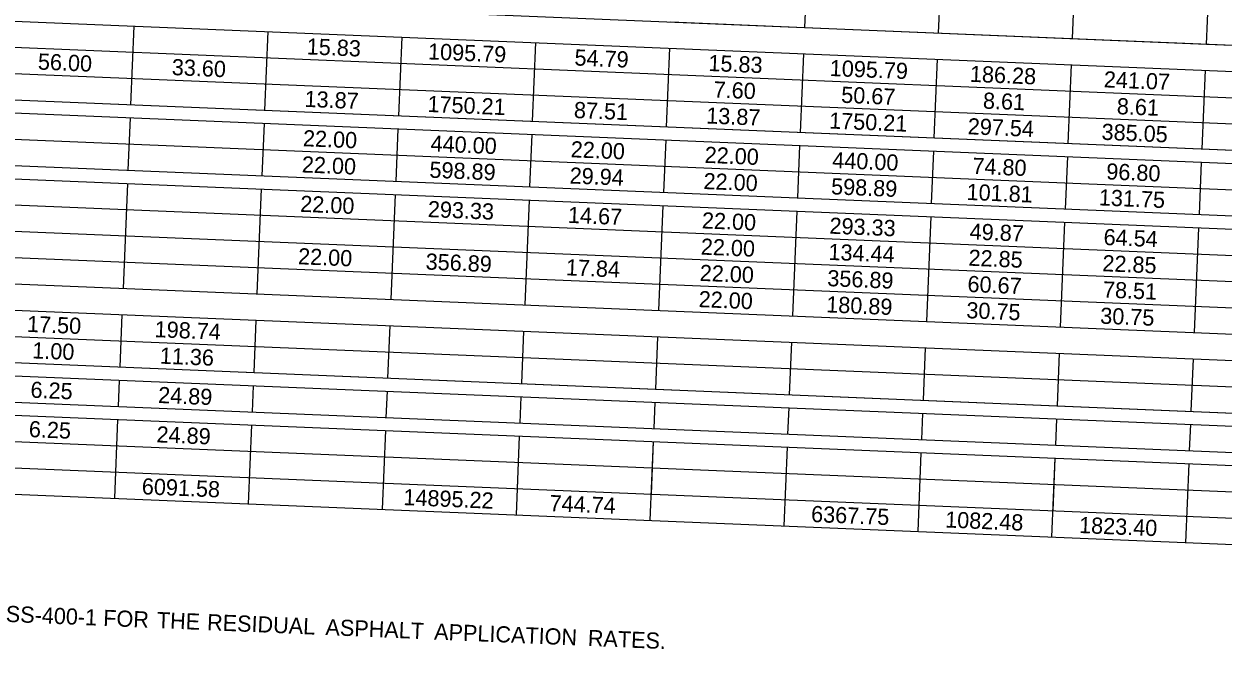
# Model space of a CAD drawing. Extents: x 1164179 to 1171425, y 1655958 to 1657208.
# Drawn here: x 1168414.3 to 1168859.2, y 1656222.8 to 1656454.9 of the extents above; entities that cross this region are included whole.
import ezdxf

# ---------------------------------------------------------------- set-up
doc = ezdxf.new("R2010")
doc.units = 0
doc.layers.add('Default', color=7, linetype='Continuous')

msp = doc.modelspace()

# ---------------------------------------------------------------- linework, layer by layer
at = {"layer": 'Default'}
for p, q in [((1168704.01, 1656453.59), (1168705.62, 1656492.56)), ((1168704.01, 1656453.59), (1168705.62, 1656492.56)), ((1168753.69, 1656451.54), (1168755.31, 1656490.51)), ((1168753.69, 1656451.54), (1168755.31, 1656490.51)), ((1168803.38, 1656449.48), (1168804.99, 1656488.45)), ((1168803.38, 1656449.48), (1168804.99, 1656488.45)), ((1168011.87, 1656482.23), (1169498.93, 1656420.71)), ((1168853.06, 1656447.43), (1168854.67, 1656486.4)), ((1168853.06, 1656447.43), (1168854.67, 1656486.4)), ((1168011.46, 1656472.49), (1169498.53, 1656410.97)), ((1168011.06, 1656462.74), (1169498.13, 1656401.23)), ((1168654.33, 1656455.65), (1168704.01, 1656453.59)), ((1168010.66, 1656453), (1169497.72, 1656391.49)), ((1168453.99, 1656424.9), (1168455.2, 1656454.13)), ((1168453.99, 1656424.9), (1168455.2, 1656454.13)), ((1168503.67, 1656422.85), (1168504.88, 1656452.07)), ((1168503.67, 1656422.85), (1168504.88, 1656452.07)), ((1168704.01, 1656453.59), (1168853.06, 1656447.43)), ((1168553.35, 1656420.79), (1168554.56, 1656450.02)), ((1168553.35, 1656420.79), (1168554.56, 1656450.02)), ((1168603.03, 1656418.74), (1168604.24, 1656447.96)), ((1168603.03, 1656418.74), (1168604.24, 1656447.96)), ((1168853.06, 1656447.43), (1169300.2, 1656428.93)), ((1168010.25, 1656443.26), (1169497.32, 1656381.74)), ((1168652.72, 1656416.68), (1168653.93, 1656445.91)), ((1168652.72, 1656416.68), (1168653.93, 1656445.91)), ((1168702.4, 1656414.63), (1168703.61, 1656443.85)), ((1168702.4, 1656414.63), (1168703.61, 1656443.85)), ((1168010.05, 1656438.39), (1169497.12, 1656376.87)), ((1168752.08, 1656412.57), (1168753.29, 1656441.8)), ((1168752.08, 1656412.57), (1168753.29, 1656441.8)), ((1168801.76, 1656410.52), (1168802.97, 1656439.74)), ((1168801.76, 1656410.52), (1168802.97, 1656439.74)), ((1168851.45, 1656408.46), (1168852.66, 1656437.69)), ((1168851.45, 1656408.46), (1168852.66, 1656437.69)), ((1168354.62, 1656429.02), (1169497.32, 1656381.74)), ((1168009.65, 1656428.65), (1169496.72, 1656367.13)), ((1168452.98, 1656400.55), (1168453.79, 1656420.03)), ((1168452.98, 1656400.55), (1168453.79, 1656420.03)), ((1168009.25, 1656418.91), (1169496.31, 1656357.39)), ((1168502.66, 1656398.5), (1168503.47, 1656417.98)), ((1168502.66, 1656398.5), (1168503.47, 1656417.98)), ((1168552.34, 1656396.44), (1168553.15, 1656415.92)), ((1168552.34, 1656396.44), (1168553.15, 1656415.92)), ((1168009.05, 1656414.04), (1169496.11, 1656352.52)), ((1168602.03, 1656394.38), (1168602.83, 1656413.87)), ((1168602.03, 1656394.38), (1168602.83, 1656413.87)), ((1168651.71, 1656392.33), (1168652.52, 1656411.81)), ((1168651.71, 1656392.33), (1168652.52, 1656411.81)), ((1168701.39, 1656390.27), (1168702.2, 1656409.76)), ((1168701.39, 1656390.27), (1168702.2, 1656409.76)), ((1168751.07, 1656388.22), (1168751.88, 1656407.7)), ((1168751.07, 1656388.22), (1168751.88, 1656407.7)), ((1168008.64, 1656404.29), (1169495.71, 1656342.78)), ((1168353.61, 1656404.66), (1169496.31, 1656357.39)), ((1168800.76, 1656386.16), (1168801.56, 1656405.65)), ((1168800.76, 1656386.16), (1168801.56, 1656405.65)), ((1168850.44, 1656384.11), (1168851.25, 1656403.59)), ((1168850.44, 1656384.11), (1168851.25, 1656403.59)), ((1168008.24, 1656394.55), (1169495.3, 1656333.04)), ((1168451.17, 1656356.71), (1168452.78, 1656395.68)), ((1168451.17, 1656356.71), (1168452.78, 1656395.68)), ((1168500.85, 1656354.66), (1168502.46, 1656393.62)), ((1168500.85, 1656354.66), (1168502.46, 1656393.62)), ((1168550.53, 1656352.6), (1168552.14, 1656391.57)), ((1168550.53, 1656352.6), (1168552.14, 1656391.57)), ((1168600.21, 1656350.55), (1168601.83, 1656389.51)), ((1168600.21, 1656350.55), (1168601.83, 1656389.51)), ((1168007.84, 1656384.81), (1169494.9, 1656323.29)), ((1168649.9, 1656348.49), (1168651.51, 1656387.46)), ((1168649.9, 1656348.49), (1168651.51, 1656387.46)), ((1168699.58, 1656346.44), (1168701.19, 1656385.4)), ((1168699.58, 1656346.44), (1168701.19, 1656385.4)), ((1168749.26, 1656344.38), (1168750.87, 1656383.35)), ((1168749.26, 1656344.38), (1168750.87, 1656383.35)), ((1168798.94, 1656342.33), (1168800.56, 1656381.29)), ((1168798.94, 1656342.33), (1168800.56, 1656381.29)), ((1168848.63, 1656340.27), (1168850.24, 1656379.24)), ((1168848.63, 1656340.27), (1168850.24, 1656379.24)), ((1168007.43, 1656375.07), (1169494.5, 1656313.55)), ((1168007.43, 1656375.07), (1169494.5, 1656313.55)), ((1168007.03, 1656365.33), (1169494.1, 1656303.81)), ((1168006.63, 1656355.59), (1169493.69, 1656294.07)), ((1168006.22, 1656345.84), (1169493.29, 1656284.33)), ((1168449.96, 1656327.49), (1168450.76, 1656346.97)), ((1168449.96, 1656327.49), (1168450.76, 1656346.97)), ((1168499.64, 1656325.43), (1168500.45, 1656344.92)), ((1168499.64, 1656325.43), (1168500.45, 1656344.92)), ((1168006.02, 1656340.97), (1169493.09, 1656279.46)), ((1168549.32, 1656323.38), (1168550.13, 1656342.86)), ((1168549.32, 1656323.38), (1168550.13, 1656342.86)), ((1168599, 1656321.32), (1168599.81, 1656340.81)), ((1168599, 1656321.32), (1168599.81, 1656340.81)), ((1168648.69, 1656319.27), (1168649.49, 1656338.75)), ((1168648.69, 1656319.27), (1168649.49, 1656338.75)), ((1168698.37, 1656317.21), (1168699.18, 1656336.69)), ((1168698.37, 1656317.21), (1168699.18, 1656336.69)), ((1168005.62, 1656331.23), (1169492.69, 1656269.71)), ((1168350.59, 1656331.6), (1169493.29, 1656284.33)), ((1168748.05, 1656315.16), (1168748.86, 1656334.64)), ((1168748.05, 1656315.16), (1168748.86, 1656334.64)), ((1168797.73, 1656313.1), (1168798.54, 1656332.58)), ((1168797.73, 1656313.1), (1168798.54, 1656332.58)), ((1168005.42, 1656326.36), (1169492.48, 1656264.84)), ((1168847.42, 1656311.05), (1168848.22, 1656330.53)), ((1168847.42, 1656311.05), (1168848.22, 1656330.53)), ((1168449.35, 1656312.88), (1168449.76, 1656322.62)), ((1168449.35, 1656312.88), (1168449.76, 1656322.62)), ((1168499.04, 1656310.82), (1168499.44, 1656320.56)), ((1168499.04, 1656310.82), (1168499.44, 1656320.56)), ((1168548.72, 1656308.76), (1168549.12, 1656318.51)), ((1168548.72, 1656308.76), (1168549.12, 1656318.51)), ((1168005.02, 1656316.62), (1169492.08, 1656255.1)), ((1168349.99, 1656316.99), (1169492.69, 1656269.71)), ((1168598.4, 1656306.71), (1168598.8, 1656316.45)), ((1168598.4, 1656306.71), (1168598.8, 1656316.45)), ((1168648.08, 1656304.65), (1168648.49, 1656314.4)), ((1168648.08, 1656304.65), (1168648.49, 1656314.4)), ((1168697.77, 1656302.6), (1168698.17, 1656312.34)), ((1168697.77, 1656302.6), (1168698.17, 1656312.34)), ((1168747.45, 1656300.54), (1168747.85, 1656310.29)), ((1168747.45, 1656300.54), (1168747.85, 1656310.29)), ((1168004.61, 1656306.88), (1169491.68, 1656245.36)), ((1168447.94, 1656278.78), (1168449.15, 1656308)), ((1168447.94, 1656278.78), (1168449.15, 1656308)), ((1168497.62, 1656276.72), (1168498.83, 1656305.95)), ((1168497.62, 1656276.72), (1168498.83, 1656305.95)), ((1168797.13, 1656298.49), (1168797.53, 1656308.23)), ((1168797.13, 1656298.49), (1168797.53, 1656308.23)), ((1168846.81, 1656296.43), (1168847.22, 1656306.17)), ((1168846.81, 1656296.43), (1168847.22, 1656306.17)), ((1168547.31, 1656274.67), (1168548.52, 1656303.89)), ((1168547.31, 1656274.67), (1168548.52, 1656303.89)), ((1168596.99, 1656272.61), (1168598.2, 1656301.84)), ((1168597.39, 1656282.36), (1168598.2, 1656301.84)), ((1168646.67, 1656270.56), (1168647.88, 1656299.78)), ((1168647.08, 1656280.3), (1168647.88, 1656299.78)), ((1168004.21, 1656297.14), (1169491.27, 1656235.62)), ((1168696.35, 1656268.5), (1168697.56, 1656297.73)), ((1168696.35, 1656268.5), (1168697.56, 1656297.73)), ((1168746.04, 1656266.45), (1168747.25, 1656295.67)), ((1168746.44, 1656276.19), (1168747.25, 1656295.67)), ((1168795.72, 1656264.39), (1168796.93, 1656293.62)), ((1168796.12, 1656274.13), (1168796.93, 1656293.62)), ((1168845.4, 1656262.34), (1168846.61, 1656291.56)), ((1168845.4, 1656262.34), (1168846.61, 1656291.56))]:
    msp.add_line(p, q, dxfattribs=at)

# ---------------------------------------------------------------- texts
for s, p in [('15.83', (1168519.11, 1656443.6)), ('1095.79', (1168564.13, 1656441.74)), ('56.00', (1168419.35, 1656437.97)), ('54.79', (1168618.47, 1656439.49)), ('15.83', (1168668.16, 1656437.44)), ('33.60', (1168469.03, 1656435.92)), ('1095.79', (1168713.18, 1656435.58)), ('186.28', (1168765.19, 1656433.42)), ('7.60', (1168670.09, 1656427.6)), ('241.07', (1168814.88, 1656431.37)), ('13.87', (1168518.3, 1656424.12)), ('50.67', (1168717.44, 1656425.64)), ('8.61', (1168770.03, 1656423.47)), ('1750.21', (1168563.91, 1656422.23)), ('87.51', (1168618.25, 1656419.99)), ('8.61', (1168819.71, 1656421.41)), ('13.87', (1168667.35, 1656417.95)), ('1750.21', (1168712.96, 1656416.07)), ('297.54', (1168764.4, 1656413.94)), ('22.00', (1168517.71, 1656409.51)), ('385.05', (1168814.05, 1656411.89)), ('440.00', (1168565.06, 1656407.55)), ('22.00', (1168617.07, 1656405.4)), ('22.00', (1168666.76, 1656403.34)), ('440.00', (1168714.11, 1656401.38)), ('22.00', (1168517.31, 1656399.77)), ('598.89', (1168564.65, 1656397.81)), ('74.80', (1168766.12, 1656399.23)), ('96.80', (1168815.8, 1656397.18)), ('29.94', (1168616.67, 1656395.66)), ('22.00', (1168666.35, 1656393.6)), ('598.89', (1168713.69, 1656391.64)), ('101.81', (1168763.96, 1656389.56)), ('131.75', (1168813.04, 1656387.53)), ('22.00', (1168516.7, 1656385.15)), ('293.33', (1168564.05, 1656383.19)), ('14.67', (1168616.06, 1656381.04)), ('22.00', (1168665.75, 1656378.99)), ('293.33', (1168713.09, 1656377.03)), ('49.87', (1168765.1, 1656374.88)), ('22.00', (1168665.35, 1656369.25)), ('64.54', (1168814.8, 1656372.82)), ('22.00', (1168515.9, 1656365.67)), ('134.44', (1168712.7, 1656367.29)), ('22.85', (1168764.68, 1656365.14)), ('356.89', (1168563.23, 1656363.71)), ('17.84', (1168615.26, 1656361.56)), ('22.85', (1168814.36, 1656363.08)), ('22.00', (1168664.94, 1656359.5)), ('356.89', (1168712.28, 1656357.55)), ('60.67', (1168764.3, 1656355.39)), ('78.51', (1168814.56, 1656353.31)), ('22.00', (1168664.54, 1656349.76)), ('180.89', (1168711.88, 1656347.8)), ('30.75', (1168763.87, 1656345.65)), ('30.75', (1168813.55, 1656343.6)), ('17.50', (1168415.32, 1656340.56)), ('198.74', (1168462.68, 1656338.6)), ('1.00', (1168417.25, 1656330.72)), ('11.36', (1168464.59, 1656328.76)), ('6.25', (1168416.61, 1656316.11)), ('24.89', (1168463.98, 1656314.15)), ('6.25', (1168416, 1656301.49)), ('24.89', (1168463.38, 1656299.53)), ('6091.58', (1168457.92, 1656280.24)), ('14895.22', (1168554.98, 1656276.23)), ('744.74', (1168609.2, 1656273.99)), ('6367.75', (1168706.27, 1656269.97)), ('1082.48', (1168756.01, 1656267.91)), ('1823.40', (1168805.71, 1656265.86)), (' SS-400-1', (1168405.21, 1656232.96)), (' FOR', (1168441.37, 1656231.46)), (' THE', (1168461.27, 1656230.64)), (' RESIDUAL', (1168479.9, 1656229.87)), (' ASPHALT', (1168523.83, 1656228.05)), (' APPLICATION', (1168564.16, 1656226.38)), (' RATES.', (1168621.19, 1656224.02))]:
    msp.add_text(s, height=6, rotation=357.6311, dxfattribs=at).set_placement(p)

doc.saveas('drawing.dxf')
